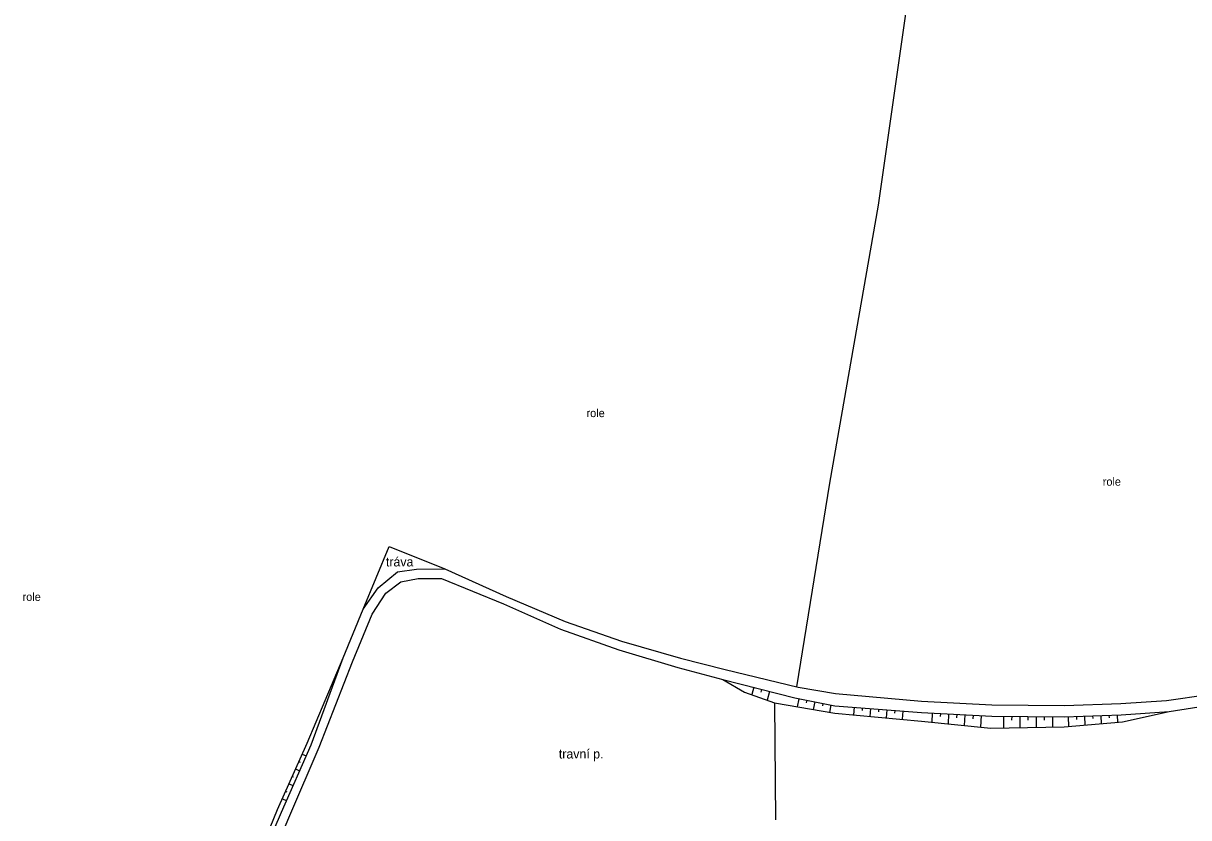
# Model space of a CAD drawing. Extents: x -661586 to -658793, y -1053889 to -1051031.
# Drawn here: x -661081.5 to -660653, y -1051788.4 to -1051496.2 of the extents above; entities that cross this region are included whole.
import ezdxf

# ---------------------------------------------------------------- set-up
doc = ezdxf.new("R2010")
doc.units = 0
for name, color, linetype in [('Vrstva 52', 7, 'Continuous'), ('Vrstva 53', 7, 'Continuous'), ('Vrstva 54', 7, 'Continuous')]:
    doc.layers.add(name, color=color, linetype=linetype)

msp = doc.modelspace()

# ---------------------------------------------------------------- linework, layer by layer
at = {"layer": 'Vrstva 52'}
for p, q in [((-660951.11, -1051703.85), (-660944, -1051698.02)), ((-660944, -1051698.02), (-660937, -1051697)), ((-660937, -1051697), (-660926.53, -1051696.89)), ((-660926.53, -1051696.89), (-660904, -1051706.99)), ((-660956.58, -1051711.68), (-660951.11, -1051703.85)), ((-660948.2, -1051705.86), (-660942.72, -1051701.59)), ((-660942.72, -1051701.59), (-660936.31, -1051700.39)), ((-660936.31, -1051700.39), (-660927.8, -1051700.44)), ((-660927.8, -1051700.44), (-660905.01, -1051709.79)), ((-660953.3, -1051713.48), (-660948.2, -1051705.86)), ((-660904, -1051706.99), (-660882.34, -1051716.19)), ((-660963.94, -1051729.61), (-660956.58, -1051711.68)), ((-660905.01, -1051709.79), (-660884.03, -1051719.07)), ((-660960.54, -1051731.01), (-660953.3, -1051713.48)), ((-660882.34, -1051716.19), (-660861.64, -1051723.47)), ((-660884.03, -1051719.07), (-660862.56, -1051726.69)), ((-660861.64, -1051723.47), (-660839.84, -1051729.71)), ((-660977.17, -1051760.98), (-660963.94, -1051729.61)), ((-660862.56, -1051726.69), (-660840.82, -1051733.11)), ((-660839.84, -1051729.71), (-660823.47, -1051733.86)), ((-660972.73, -1051762.49), (-660960.54, -1051731.01)), ((-660840.82, -1051733.11), (-660824.31, -1051737.52)), ((-660823.47, -1051733.86), (-660796.61, -1051740.392)), ((-660824.31, -1051737.52), (-660816.34, -1051742.19)), ((-660816.34, -1051742.19), (-660805.3, -1051746.13)), ((-660796.61, -1051740.392), (-660782.88, -1051742.72)), ((-660782.88, -1051742.72), (-660751.25, -1051745.59)), ((-660661.14, -1051745.34), (-660645.9, -1051743.08)), ((-660805.3, -1051746.13), (-660783.08, -1051750.01)), ((-660751.25, -1051745.59), (-660725.37, -1051746.94)), ((-660725.37, -1051746.94), (-660698.73, -1051747.17)), ((-660698.73, -1051747.17), (-660677.92, -1051746.35)), ((-660677.92, -1051746.35), (-660661.14, -1051745.34)), ((-660660.15, -1051749.3), (-660645.39, -1051746.99)), ((-660783.08, -1051750.01), (-660751.3, -1051752.84)), ((-660677.41, -1051753.19), (-660660.15, -1051749.3)), ((-660751.3, -1051752.84), (-660725.74, -1051755.53)), ((-660725.74, -1051755.53), (-660698.84, -1051754.98)), ((-660698.84, -1051754.98), (-660677.41, -1051753.19)), ((-660988.12, -1051785.41), (-660977.17, -1051760.98)), ((-660983.56, -1051787.64), (-660972.73, -1051762.49)), ((-661015.38, -1051852.91), (-660988.12, -1051785.41)), ((-661011.79, -1051853.99), (-660983.56, -1051787.64))]:
    msp.add_line(p, q, dxfattribs=at)
at = {"layer": 'Vrstva 53'}
for p, q in [((-660767.07, -1051563.12), (-660753.96, -1051471.18)), ((-660785.02, -1051665.31), (-660767.07, -1051563.12)), ((-660797.15, -1051740.3), (-660785.02, -1051665.31)), ((-660956.58, -1051711.68), (-660947.03, -1051688.64)), ((-660947.03, -1051688.64), (-660926.53, -1051696.89)), ((-660975.74, -1051761.56), (-660963.94, -1051729.61)), ((-660824.31, -1051737.52), (-660797.88, -1051744.33)), ((-660805.3, -1051746.13), (-660805.007, -1051789.179)), ((-660797.88, -1051744.33), (-660783.1, -1051747.21)), ((-660783.1, -1051747.21), (-660751.25, -1051749.71)), ((-660751.25, -1051749.71), (-660725.36, -1051751.01)), ((-660725.36, -1051751.01), (-660698.87, -1051751.31)), ((-660698.87, -1051751.31), (-660677.8, -1051750.53)), ((-660677.8, -1051750.53), (-660660.15, -1051749.3)), ((-660986.61, -1051786.33), (-660975.74, -1051761.56)), ((-661015.38, -1051852.91), (-660986.61, -1051786.33))]:
    msp.add_line(p, q, dxfattribs=at)
at = {"layer": 'Vrstva 54'}
for p, q in [((-660812.961, -1051740.444), (-660813.657, -1051743.147)), ((-660810.055, -1051741.193), (-660810.31, -1051742.181)), ((-660807.15, -1051741.941), (-660807.983, -1051745.173)), ((-660796.379, -1051744.622), (-660796.957, -1051747.587)), ((-660793.435, -1051745.196), (-660793.623, -1051746.164)), ((-660790.49, -1051745.77), (-660791.045, -1051748.619)), ((-660787.545, -1051746.344), (-660787.727, -1051747.273)), ((-660784.601, -1051746.918), (-660785.133, -1051749.651)), ((-660776.028, -1051747.765), (-660776.252, -1051750.618)), ((-660773.037, -1051748), (-660773.113, -1051748.96)), ((-660770.047, -1051748.235), (-660770.276, -1051751.15)), ((-660767.056, -1051748.469), (-660767.133, -1051749.451)), ((-660764.065, -1051748.704), (-660764.299, -1051751.682)), ((-660761.074, -1051748.939), (-660761.153, -1051749.941)), ((-660758.083, -1051749.174), (-660758.322, -1051752.215)), ((-660747.317, -1051749.908), (-660747.484, -1051753.242)), ((-660744.32, -1051750.058), (-660744.379, -1051751.223)), ((-660741.324, -1051750.208), (-660741.508, -1051753.871)), ((-660738.328, -1051750.359), (-660738.392, -1051751.633)), ((-660735.332, -1051750.509), (-660735.532, -1051754.499)), ((-660732.335, -1051750.66), (-660732.405, -1051752.043)), ((-660729.339, -1051750.81), (-660729.556, -1051755.128)), ((-660721.114, -1051751.058), (-660721.164, -1051755.436)), ((-660718.115, -1051751.092), (-660718.131, -1051752.518)), ((-660715.115, -1051751.126), (-660715.162, -1051755.314)), ((-660712.115, -1051751.16), (-660712.13, -1051752.523)), ((-660709.115, -1051751.194), (-660709.16, -1051755.191)), ((-660706.115, -1051751.228), (-660706.13, -1051752.527)), ((-660703.116, -1051751.262), (-660703.159, -1051755.068)), ((-660697.329, -1051751.253), (-660697.196, -1051754.843)), ((-660694.331, -1051751.142), (-660694.288, -1051752.291)), ((-660691.333, -1051751.031), (-660691.21, -1051754.343)), ((-660688.335, -1051750.92), (-660688.296, -1051751.977)), ((-660685.337, -1051750.809), (-660685.225, -1051753.843)), ((-660682.339, -1051750.698), (-660682.303, -1051751.662)), ((-660679.341, -1051750.587), (-660679.239, -1051753.343)), ((-660980.191, -1051767.72), (-660979.705, -1051767.938)), ((-660978.964, -1051764.982), (-660977.525, -1051765.627)), ((-660981.418, -1051770.457), (-660979.936, -1051771.122)), ((-660983.872, -1051775.933), (-660982.347, -1051776.616)), ((-660982.645, -1051773.195), (-660982.144, -1051773.419)), ((-660986.326, -1051781.408), (-660984.758, -1051782.11)), ((-660985.099, -1051778.67), (-660984.584, -1051778.901))]:
    msp.add_line(p, q, dxfattribs=at)

# ---------------------------------------------------------------- texts
at = {"layer": 'Vrstva 52'}
for p in [(-660874.44, -1051641.048), (-660684.627, -1051666.289), (-661081.803, -1051708.66)]:
    msp.add_text('role', height=3, dxfattribs=at).set_placement(p)
at = {"layer": 'Vrstva 53'}
for s, p in [('tráva', (-660948.202, -1051695.976)), ('travní p.', (-660884.621, -1051766.63))]:
    msp.add_text(s, height=3.4, dxfattribs=at).set_placement(p)

doc.saveas('drawing.dxf')
